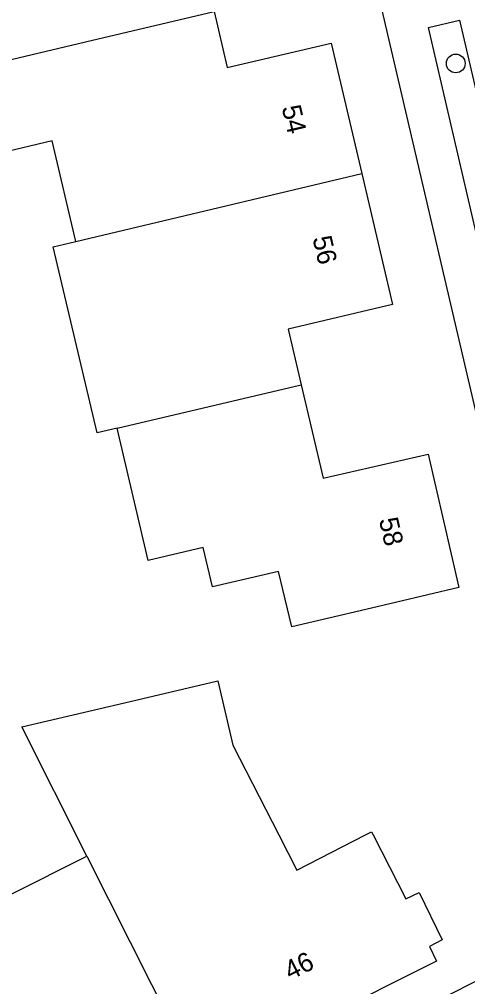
# Model space of a CAD drawing. Extents: x 157321 to 158827, y 386650 to 388532.
# Drawn here: x 157721.3 to 157744.7, y 387742.1 to 387792.6 of the extents above; entities that cross this region are included whole.
import ezdxf

# ---------------------------------------------------------------- set-up
doc = ezdxf.new("R2010")
doc.units = 0
for name, color, linetype in [('IMGEO_Boom', 7, 'Continuous'), ('IMGEO_Pand', 7, 'Continuous'), ('IMGEO_Pand_nummerreeks', 7, 'Continuous'), ('IMGEO_Voetpad_open', 7, 'Continuous')]:
    doc.layers.add(name, color=color, linetype=linetype)

msp = doc.modelspace()

# ---------------------------------------------------------------- linework, layer by layer
at = {"layer": 'IMGEO_Boom'}
msp.add_circle((157744.11, 387790.25), 0.489, dxfattribs=at)
at = {"layer": 'IMGEO_Pand'}
for points in [[(157724.276, 387780.962), (157723.043, 387786.206), (157718.424, 387785.121), (157717.365, 387789.63), (157721.983, 387790.718), (157724.773, 387791.375), (157726.627, 387791.811), (157731.494, 387792.954), (157732.178, 387790.04), (157737.597, 387791.314), (157739.2, 387784.5)], [(157724.276, 387780.962), (157739.2, 387784.5)], [(157739.2, 387784.5), (157740.806, 387777.669), (157735.355, 387776.387), (157736.04, 387773.476)], [(157726.426, 387771.223), (157725.378, 387770.976), (157723.087, 387780.681), (157724.276, 387780.962)], [(157736.04, 387773.476), (157737.184, 387768.614), (157742.673, 387769.858), (157744.275, 387762.899), (157739.408, 387761.754), (157735.543, 387760.845), (157734.861, 387763.746), (157731.415, 387762.935), (157730.929, 387764.999), (157728.049, 387764.318), (157726.426, 387771.223)], [(157726.426, 387771.223), (157736.04, 387773.476)], [(157724.847, 387748.893), (157721.455, 387755.635), (157726.811, 387756.893), (157731.678, 387758.035), (157732.47, 387754.685), (157734.865, 387750), (157735.804, 387748.162), (157739.402, 387750), (157739.713, 387750.159), (157739.794, 387750), (157741.51, 387746.652), (157742.193, 387746.988), (157743.4, 387744.512), (157742.744, 387744.177), (157743.104, 387743.403), (157737.032, 387740.358), (157737.888, 387738.654)], [(157723.663, 387731.515), (157721.347, 387735.947), (157716.862, 387744.885), (157724.847, 387748.893)], [(157724.847, 387748.893), (157731.591, 387735.493)]]:
    msp.add_lwpolyline(points, dxfattribs=at)
at = {"layer": 'IMGEO_Voetpad_open'}
for points in [[(157751.274, 387746.222), (157750.377, 387750), (157747.568, 387761.828), (157732.841, 387824.842)], [(157745.634, 387779.462), (157742.682, 387792.118), (157744.307, 387792.5), (157747.264, 387779.843), (157745.634, 387779.462)], [(157737.888, 387738.654), (157750.993, 387745.339)]]:
    msp.add_lwpolyline(points, dxfattribs=at)

# ---------------------------------------------------------------- texts
at = {"layer": 'IMGEO_Pand_nummerreeks'}
for s, rotation, p in [('54', 283.2351, (157735.016, 387787.957)), ('56', 283.2342, (157736.622, 387781.134)), ('58', 282.9639, (157740.093, 387766.445)), ('46', 26.633, (157735.471, 387742.393))]:
    msp.add_text(s, height=1, rotation=rotation, dxfattribs=at).set_placement(p)

doc.saveas('drawing.dxf')
